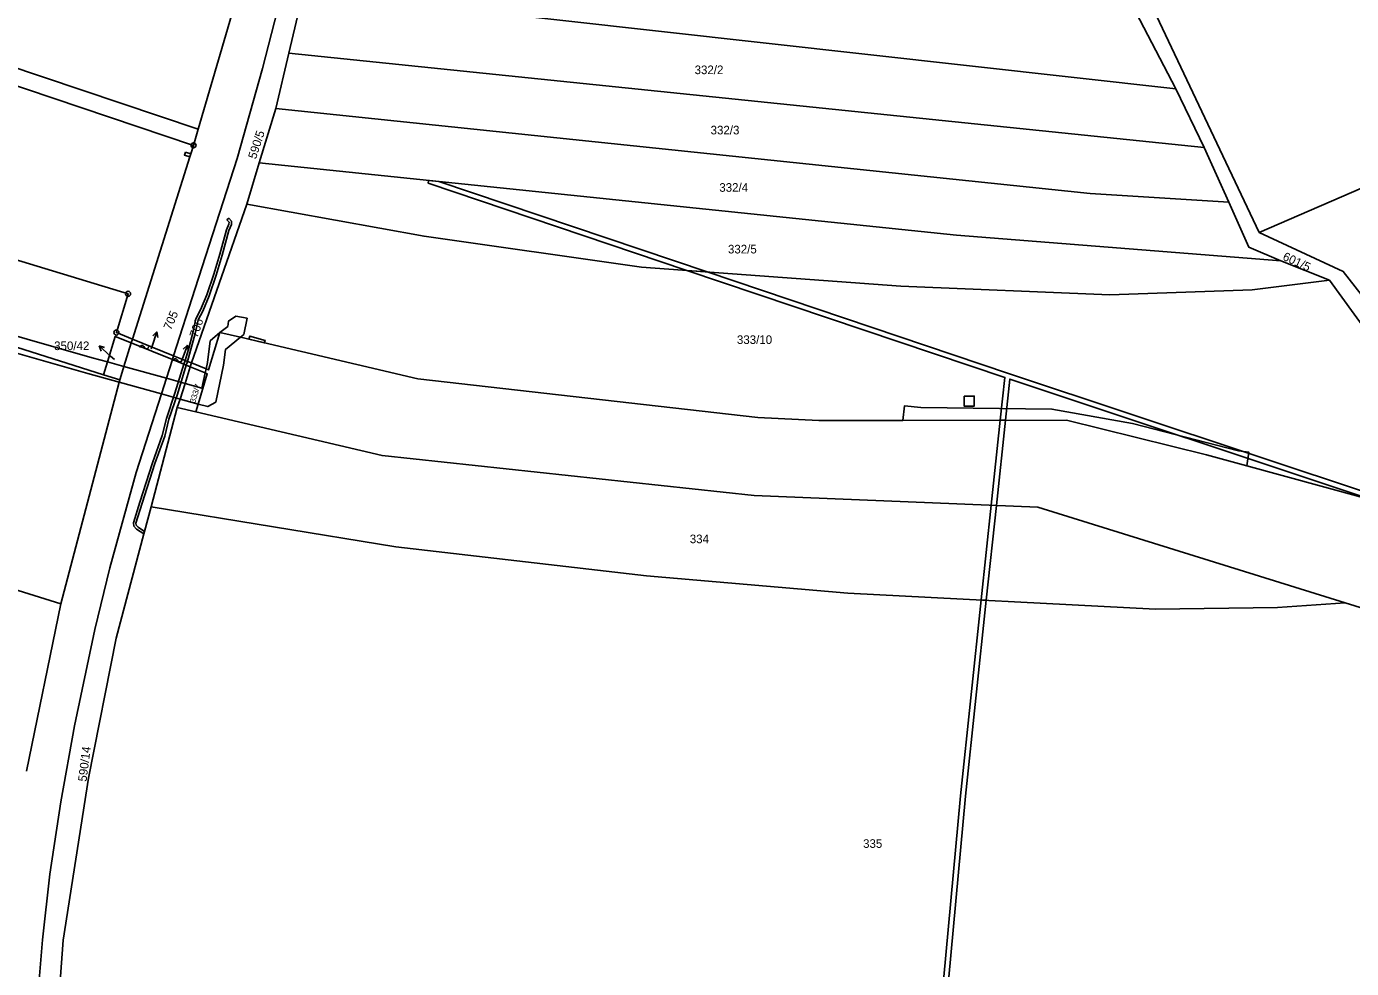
# Model space of a CAD drawing. Extents: x -758582 to -751794, y -998770 to -994350.
# Drawn here: x -755912.3 to -755650.6, y -994983.3 to -994797.3 of the extents above; entities that cross this region are included whole.
import ezdxf

# ---------------------------------------------------------------- set-up
doc = ezdxf.new("R2010")
doc.units = 0
for name, color, linetype in [('Hranice parcel', 7, 'Continuous'), ('Parcelní čísla', 7, 'Continuous'), ('Pop  PČ popisy', 7, 'Continuous'), ('Věcná břemena k části', 7, 'Continuous'), ('Značky bodu BP', 7, 'Continuous'), ('Značky budov', 7, 'Continuous')]:
    doc.layers.add(name, color=color, linetype=linetype)

msp = doc.modelspace()

# ---------------------------------------------------------------- linework, layer by layer
at = {"layer": 'Hranice parcel'}
for p, q in [((-755668.84, -994837.94), (-755692.66, -994787.61)), ((-755860.46, -994802.54), (-755857.6, -994790.33)), ((-755685.31, -994809.56), (-755857.6, -994790.33)), ((-755695.28, -994790.45), (-755685.31, -994809.56)), ((-755584.49, -994801.38), (-755668.84, -994837.94)), ((-755863.06, -994813.48), (-755860.46, -994802.54)), ((-755860.46, -994802.54), (-755679.7, -994821.18)), ((-755685.31, -994809.56), (-755679.7, -994821.18)), ((-755866.32, -994824.18), (-755863.06, -994813.48)), ((-755878.36, -994817.53), (-755879.3, -994820.73)), ((-755679.7, -994821.18), (-755674.88, -994831.94)), ((-755868.77, -994832.38), (-755866.32, -994824.18)), ((-755879.71, -994863.71), (-755868.77, -994832.38)), ((-755664.59, -994843.56), (-755655, -994847.35)), ((-755883.23, -994862.29), (-755878.96, -994849)), ((-755655, -994847.35), (-755628.81, -994883.42)), ((-755905.48, -994911.3), (-756086.25, -994854.78)), ((-755894.52, -994857.69), (-755891.37, -994858.98)), ((-755891.61, -994859.74), (-755891.37, -994858.98)), ((-755891.37, -994858.98), (-755883.23, -994862.29)), ((-755874.1, -994857.67), (-755876.34, -994865.08)), ((-755883.47, -994863.05), (-755891.61, -994859.74)), ((-755883.23, -994862.29), (-755883.47, -994863.05)), ((-755879.95, -994864.48), (-755879.71, -994863.71)), ((-755897.05, -994866.03), (-755893.83, -994867.05)), ((-755767.88, -994874.47), (-755834.98, -994866.84)), ((-755887.69, -994892.13), (-755882.5, -994872.54)), ((-755882.5, -994872.54), (-755878.86, -994873.39)), ((-755679.24, -994881.84), (-755706.92, -994875)), ((-755905.48, -994911.3), (-755912.3, -994944.36))]:
    msp.add_line(p, q, dxfattribs=at)
for points in [[(-755878.96, -994849), (-755870.67, -994823.33), (-755865.69, -994805.58), (-755862.15, -994791.68), (-755859.25, -994779.21), (-755854.8, -994756.88), (-755851.64, -994736.31), (-755849.48, -994713), (-755848.56, -994686.36), (-755848.37, -994672.01), (-755848.1, -994670.32), (-755847.04, -994668.89)], [(-755861.28, -994747.52), (-755865.2, -994772.6), (-755878.36, -994817.53)], [(-756070.72, -994760.05), (-756053.87, -994764.58), (-756035.07, -994770.23), (-756011.64, -994777.98), (-755956.83, -994794.65), (-755879.3, -994820.73)], [(-755878.36, -994817.53), (-755955, -994791.7), (-756000, -994778.26)], [(-756071.25, -994800.04), (-756053.14, -994801.16), (-755892.22, -994850.06), (-755894.52, -994857.69)], [(-756073.22, -994814.18), (-756055.93, -994815.59), (-755897.05, -994866.03)], [(-755863.06, -994813.48), (-755702.22, -994830.23), (-755674.88, -994831.94)], [(-755879.3, -994820.73), (-755879.84, -994822.43), (-755880.02, -994823), (-755891.37, -994858.98)], [(-755866.32, -994824.18), (-755728.61, -994838.47), (-755664.59, -994843.56)], [(-755868.77, -994832.38), (-755833.78, -994838.7), (-755790.86, -994844.76), (-755739.63, -994848.56), (-755698.32, -994850.24), (-755670.26, -994849.26), (-755655, -994847.35)], [(-755674.88, -994831.94), (-755670.88, -994840.85), (-755664.59, -994843.56)], [(-755668.84, -994837.94), (-755652.27, -994845.64), (-755621.26, -994885.26)], [(-755891.61, -994859.74), (-755894.76, -994858.46), (-755896.29, -994863.5), (-755897.05, -994866.03)], [(-755834.98, -994866.84), (-755870.03, -994858.62), (-755874.1, -994857.67)], [(-755893.83, -994867.05), (-755893.03, -994864.4), (-755891.61, -994859.74)], [(-755890.62, -994885.32), (-755885.64, -994869.81), (-755884.65, -994866.72), (-755883.47, -994863.05)], [(-755883.47, -994863.05), (-755881.21, -994863.97), (-755880.74, -994864.16), (-755879.95, -994864.48)], [(-755883.23, -994862.29), (-755880.97, -994863.2), (-755880.5, -994863.39), (-755879.71, -994863.71)], [(-755879.95, -994864.48), (-755880.98, -994867.74), (-755881.96, -994870.83), (-755882.5, -994872.54)], [(-755878.86, -994873.39), (-755878.38, -994871.82), (-755876.58, -994865.85), (-755876.99, -994865.68), (-755879.95, -994864.48)], [(-755876.34, -994865.08), (-755876.82, -994864.89), (-755879.71, -994863.71)], [(-755893.83, -994867.05), (-755893.95, -994867.51), (-755905.48, -994911.3)], [(-755878.86, -994873.39), (-755842.07, -994882.02), (-755768.6, -994889.88), (-755712.56, -994892.17), (-755651.86, -994911.06)], [(-755706.92, -994875), (-755739.23, -994875.06), (-755755.79, -994875.09), (-755767.88, -994874.47)], [(-755648.91, -994890.16), (-755671.27, -994884.03), (-755679.24, -994881.84)], [(-755910.93, -995004.26), (-755910.45, -994993.47), (-755909.13, -994977.63), (-755907.64, -994964.67), (-755905.47, -994950.38), (-755902.8, -994935.39), (-755898.77, -994916.35), (-755895.8, -994904.16), (-755890.62, -994885.32)], [(-755907.16, -995006.38), (-755905.06, -994977.72), (-755900.01, -994945.74), (-755894.56, -994918.09), (-755889.11, -994897.48), (-755888.98, -994896.98), (-755887.69, -994892.13)], [(-755887.69, -994892.13), (-755839.34, -994900), (-755789.82, -994905.77), (-755750.06, -994909.15), (-755689.3, -994912.31), (-755665.27, -994912), (-755651.86, -994911.06)], [(-755651.86, -994911.06), (-755606.26, -994925.26), (-755575.48, -994966.53)]]:
    msp.add_lwpolyline(points, dxfattribs=at)
at = {"layer": 'Pop  PČ popisy'}
for p, q in [((-755887.46, -994860.4), (-755886.53, -994857.55)), ((-755886.53, -994857.55), (-755887.32, -994858.34)), ((-755886.53, -994857.55), (-755886.37, -994858.65)), ((-755895.7, -994862.34), (-755897.93, -994860.33)), ((-755897.93, -994860.33), (-755896.85, -994860.63)), ((-755897.93, -994860.33), (-755897.52, -994861.37)), ((-755887.63, -994860.92), (-755887.46, -994860.4)), ((-755881.56, -994863.01), (-755880.48, -994860.21)), ((-755880.48, -994860.21), (-755881.31, -994860.96)), ((-755880.48, -994860.21), (-755880.38, -994861.32)), ((-755894.92, -994863.06), (-755895.7, -994862.34)), ((-755881.7, -994863.37), (-755881.56, -994863.01))]:
    msp.add_line(p, q, dxfattribs=at)
at = {"layer": 'Věcná břemena k části'}
for points in [[(-756088.72, -994825.18), (-756088.76, -994828.38), (-756079.17, -994829.59), (-756073.22, -994814.18), (-756055.93, -994815.59), (-755897.05, -994866.03), (-755893.83, -994867.05), (-755893.03, -994864.4), (-755896.29, -994863.5), (-755899.3, -994862.67), (-755925.08, -994855.31), (-755970.88, -994840.97), (-756016.69, -994826.72), (-756039.51, -994819.46), (-756051.05, -994815.89), (-756057.79, -994814.43), (-756063.16, -994813.8), (-756074.11, -994813.66), (-756078.96, -994825.73), (-756079.69, -994826.35)], [(-755893.95, -994867.51), (-755893.83, -994867.05), (-755897.05, -994866.03), (-756055.93, -994815.59), (-756073.22, -994814.18), (-756079.17, -994829.59), (-756078.6, -994829.66), (-756076.25, -994827.69), (-756071.94, -994816.93), (-756063.37, -994817.04), (-756058.32, -994817.63), (-756051.89, -994819.03), (-756040.48, -994822.55), (-756017.66, -994829.81), (-755971.85, -994844.06), (-755926.01, -994858.42), (-755900.18, -994865.79)], [(-755880.9, -994822.09), (-755881.08, -994822.66), (-755880.02, -994823), (-755879.84, -994822.43)], [(-755832.96, -994828.21), (-755781.86, -994845.43), (-755777.85, -994845.73), (-755830.87, -994827.86), (-755832.9, -994827.65)], [(-755872.32, -994835.12), (-755872.69, -994835.45), (-755872.29, -994835.9), (-755872.31, -994836.28), (-755872.78, -994837.42), (-755874.11, -994842.25), (-755875.29, -994846.19), (-755876.67, -994850.28), (-755877.91, -994853.25), (-755878.85, -994854.99), (-755879.45, -994857.76), (-755880.31, -994861.06), (-755880.97, -994863.2), (-755881.21, -994863.97), (-755882.97, -994869.69), (-755884.62, -994874.68), (-755885.47, -994878.05), (-755887.4, -994883.44), (-755889.9, -994891.22), (-755891.16, -994895.31), (-755891.1, -994895.92), (-755890.58, -994896.55), (-755889.11, -994897.48), (-755888.98, -994896.98), (-755890.24, -994896.17), (-755890.62, -994895.72), (-755890.66, -994895.37), (-755889.42, -994891.38), (-755886.92, -994883.6), (-755884.99, -994878.19), (-755884.14, -994874.82), (-755882.49, -994869.85), (-755880.74, -994864.16), (-755880.5, -994863.39), (-755878.97, -994857.88), (-755878.37, -994855.17), (-755877.45, -994853.47), (-755876.21, -994850.46), (-755874.81, -994846.35), (-755873.63, -994842.39), (-755872.3, -994837.58), (-755871.81, -994836.38), (-755871.79, -994835.72)], [(-755718.38, -994865.76), (-755777.85, -994845.73), (-755781.86, -994845.43), (-755719.08, -994866.58), (-755719.98, -994875.02), (-755718.97, -994875.02), (-755718.11, -994866.9), (-755648.3, -994890.12), (-755645.69, -994889.93)], [(-755869.36, -994858.07), (-755868.73, -994854.89), (-755870.96, -994854.5), (-755872.37, -994855.44), (-755872.52, -994856.49), (-755874.1, -994857.67), (-755870.03, -994858.62)], [(-755884.65, -994866.72), (-755885.64, -994869.81), (-755881.96, -994870.83), (-755878.38, -994871.82), (-755876.5, -994872.34), (-755874.92, -994871.44), (-755873.35, -994864.14), (-755872.96, -994861.03), (-755870.03, -994858.62), (-755874.1, -994857.67), (-755876.34, -994865.08), (-755876.82, -994864.89), (-755876.99, -994865.68), (-755877.64, -994868.66), (-755880.98, -994867.74)], [(-755874.1, -994857.67), (-755876.01, -994859.35), (-755876.54, -994863.6), (-755876.82, -994864.89), (-755876.34, -994865.08)], [(-755865.32, -994859.72), (-755865.18, -994859.25), (-755868.16, -994858.39), (-755868.35, -994859.01)], [(-755893.03, -994864.4), (-755893.95, -994867.51), (-755885.64, -994869.81), (-755884.65, -994866.72)], [(-755671.27, -994884.03), (-755670.9, -994881.32), (-755672.91, -994881.04), (-755693.87, -994875.67), (-755709.79, -994872.83), (-755735.67, -994872.54), (-755738.87, -994872.15), (-755739.23, -994875.06), (-755706.92, -994875), (-755679.24, -994881.84)], [(-755727.13, -994870.24), (-755727.13, -994872.24), (-755725.13, -994872.24), (-755725.13, -994870.24)], [(-755719.98, -994875.02), (-755721.76, -994891.79), (-755720.76, -994891.83), (-755718.97, -994875.02)], [(-755722.75, -994910.57), (-755720.76, -994891.83), (-755721.76, -994891.79), (-755723.75, -994910.52)], [(-755734, -995027.23), (-755726.87, -994949.28), (-755722.75, -994910.57), (-755723.75, -994910.52), (-755727.87, -994949.18), (-755734.99, -995027.14)]]:
    msp.add_lwpolyline(points, close=True, dxfattribs=at)
at = {"layer": 'Značky bodu BP'}
for centre, radius in [((-755879.3, -994820.73), 0.5), ((-755879.3, -994820.73), 0.0303), ((-755892.22, -994850.06), 0.5), ((-755892.22, -994850.06), 0.0303), ((-755894.52, -994857.69), 0.5), ((-755894.52, -994857.69), 0.0303)]:
    msp.add_circle(centre, radius, dxfattribs=at)
at = {"layer": 'Značky budov'}
for p, q in [((-755889.09, -994860.46), (-755888.89, -994860.72)), ((-755882.53, -994863.07), (-755882.33, -994863.33))]:
    msp.add_line(p, q, dxfattribs=at)
for centre, start, end in [((-755889.43, -994860.65), 29.2914, 181.2189), ((-755888.55, -994860.53), 209.2914, 1.2189), ((-755882.87, -994863.26), 29.2914, 181.2189), ((-755881.99, -994863.14), 209.2914, 1.2189)]:
    msp.add_arc(centre, 0.394, start, end, dxfattribs=at)

# ---------------------------------------------------------------- texts
at = {"layer": 'Parcelní čísla'}
for s, p in [('332/2', (-755780.35, -994806.67)), ('332/3', (-755777.19, -994818.57)), ('332/4', (-755775.47, -994829.9)), ('332/5', (-755773.76, -994842.08)), ('350/42', (-755906.82, -994861.17)), ('333/10', (-755771.99, -994859.96)), ('334', (-755781.3, -994899.31)), ('335', (-755747.08, -994959.48))]:
    msp.add_text(s, height=1.7, dxfattribs=at).set_placement(p)
for s, height, rotation, p in [('590/5', 1.7, 72, (-755866.96, -994823.56)), ('601/5', 1.7, 335, (-755664.36, -994843.28)), ('705', 1.7, 67, (-755883.75, -994857.35)), ('706', 1.7, 71, (-755878.55, -994858.86)), ('333/7', 1.14, 73, (-755878.98, -994871.73)), ('590/14', 1.7, 83, (-755900.43, -994946.47))]:
    msp.add_text(s, height=height, rotation=rotation, dxfattribs=at).set_placement(p)

doc.saveas('drawing.dxf')
